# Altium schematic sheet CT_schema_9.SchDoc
size 287 x 160 mm
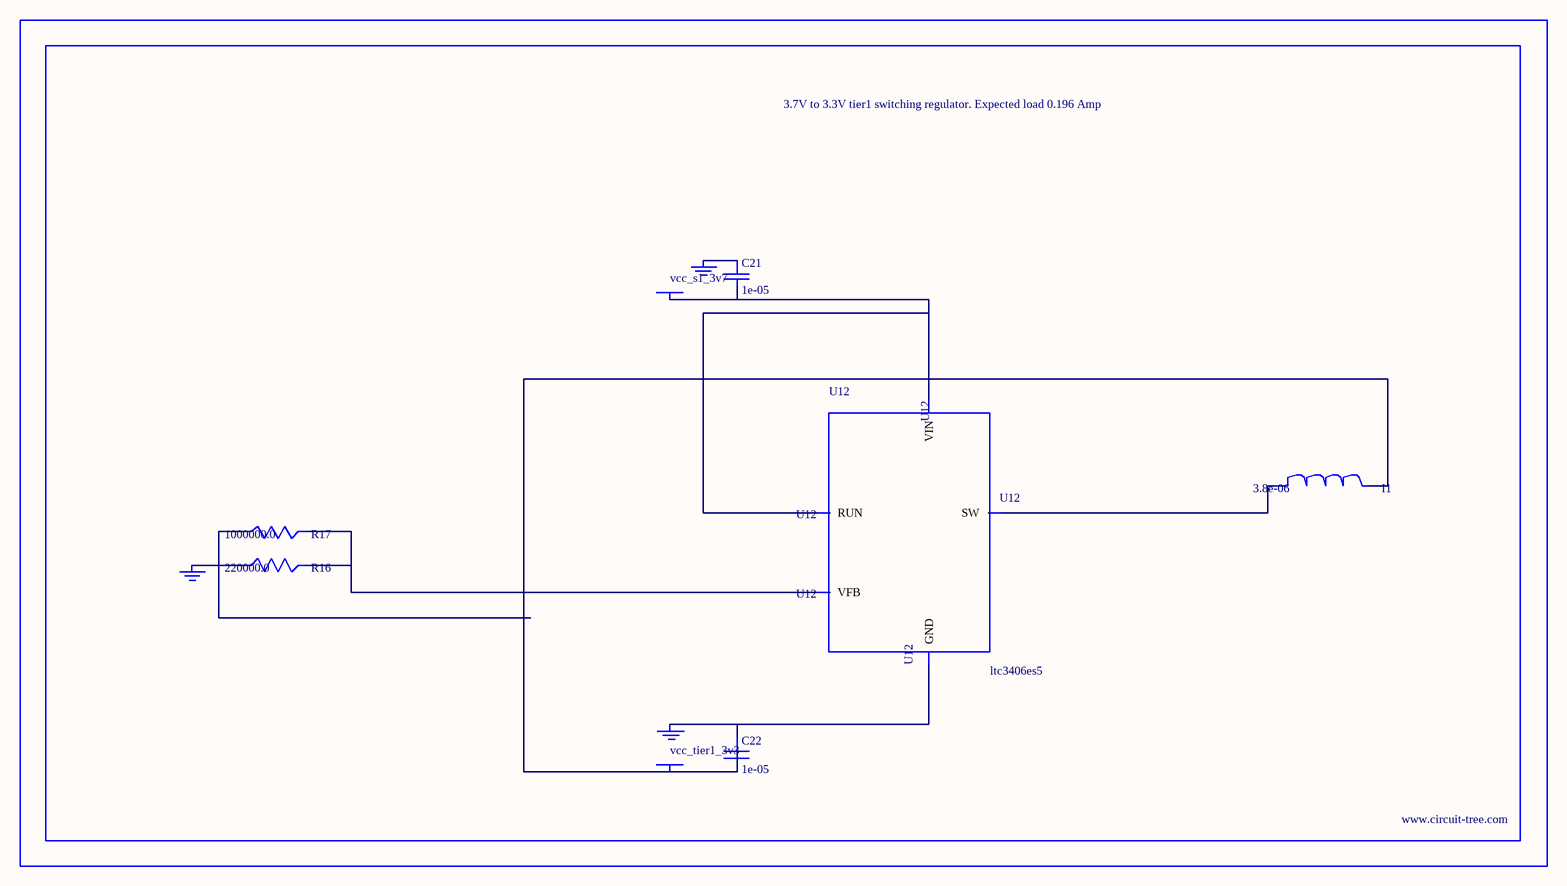
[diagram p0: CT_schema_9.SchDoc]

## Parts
BORDER8  (no value)
C21  1e-05  [C0805]
C22  1e-05  [C0805]
GND_INSTANCE_8_0  (no value)
GND_INSTANCE_8_1  (no value)
GND_INSTANCE_8_2  (no value)
I1  3.8e-06  [DR1040]
POWER_INSTANCE_8_0  vcc_tier1_3v3
POWER_INSTANCE_8_1  vcc_s1_3v7
R16  220000.0  [R0603]
R17  1000000.0  [R0603]
U12  ltc3406es5  [TSOT-23-5]

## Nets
NetC21_1: C21.1 GND_INSTANCE_8_1.0(GND)
NetC21_2: C21.2 POWER_INSTANCE_8_1.0(PWR) U12.1(RUN) U12.4(VIN)
NetC22_1: C22.1 GND_INSTANCE_8_0.0(GND) U12.2(GND)
NetC22_2: C22.2 I1.2 POWER_INSTANCE_8_0.0(PWR) R17.1
NetGND_INSTANCE_8_2_0: GND_INSTANCE_8_2.0(GND) R16.1
NetI1_1: I1.1 U12.3(SW)
NetR16_2: R16.2 R17.2 U12.5(VFB)

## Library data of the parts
BORDER8 = BORDER_PAGE8
C21 C22 = C0805C106K8RACTU
GND_INSTANCE_8_0-GND_INSTANCE_8_2 = GND
I1 = DR1040-3R8-R
POWER_INSTANCE_8_0 POWER_INSTANCE_8_1 = PWR
R16 = RC0603JR-07220KL
R17 = RC0603JR-071ML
